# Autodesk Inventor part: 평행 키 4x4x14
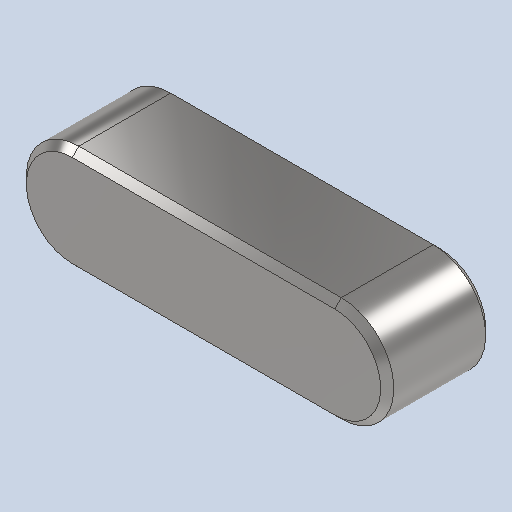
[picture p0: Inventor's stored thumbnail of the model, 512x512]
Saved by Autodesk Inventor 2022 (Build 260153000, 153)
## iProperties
Created: 2024-12
Part Number: 평행 키 4x4x14
Material: 강철, 연강
Description: 키 및 해당 키홈
Document SubType Name: Modeling
Designer: PC-12
Density: 7.85 g/cm^3
Appearance: 기본값
Author: jhkim
Sending System: Autodesk Inventor 2025
Preprocessor: ST-DEVELOPER v20
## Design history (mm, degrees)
node "평행 키 4x4x141"
node "솔리드1"
body "Solid1"
